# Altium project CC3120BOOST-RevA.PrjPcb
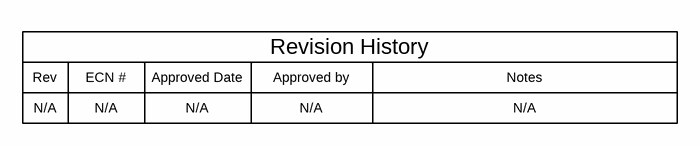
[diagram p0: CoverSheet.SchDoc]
CopyrightYear: 2015; EVM_Orderable: CC3120BOOST; PCB_Layout: Tessolve; PCB_Rev: A; PRJ_Customer: Public Release; PRJ_Engineer: Prajay Madhavan; PRJ_Number: WCS001; PRJ_Title: CC3120BOOST; SCH_Rev: A; TechSupport: http://www.ti.com/support; TID: N/A
4 sheets, 156 parts. Net scope: global (net labels, ports and power ports of the same name join across sheets).
Board file: CC3120BOOST-RevA.PcbDoc
Sheets:
  CoverSheet.SchDoc
  1.Engine.SchDoc
  2.HOST INTERFACE.SchDoc
  EVM_Hardware.SchDoc

## Sheet CoverSheet.SchDoc: Cover Sheet
size 431 x 279 mm; Date: Not shown in title block; ApprovedBy: Not shown in title block; CheckedBy: Not shown in title block; Author: Not shown in title block; CompanyName: Not shown in title block; Engineer: Not shown in title block; Organization: Not shown in title block; Address1: Not shown in title block; Address2: Not shown in title block; Address3: Not shown in title block; Address4: Not shown in title block; DocumentNumber: 1; Revision: Use project parameter SCH_Rev; SheetNumber: 1; SheetTotal: 4; PageSetup: Record=PageOptions¦CenterHorizontal=True¦CenterVertical=True¦PrintScale=1.00¦XCorrection=1.00¦YCorrection=1.00¦PrintKind=0¦BorderSize=5000000¦LeftOffset=0¦BottomOffset=0¦Orientation=2¦PaperLength=1000¦PaperWidth=1000¦Scale=100¦PaperSource=15¦PrintQuality=600¦MediaType=1¦DitherType=10¦PaperKind=Letter¦PrintScaleMode=1

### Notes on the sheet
- Rev
- N/A
- ECN #
- Approved Date
- Approved by
- Revision History
- Notes

## Sheet 1.Engine.SchDoc: Engine
size 558 x 431 mm; Date: Not shown in title block; ApprovedBy: Not shown in title block; CheckedBy: Not shown in title block; Author: Not shown in title block; CompanyName: Not shown in title block; Engineer: Not shown in title block; Organization: Not shown in title block; Address1: Not shown in title block; Address2: Not shown in title block; Address3: Not shown in title block; Address4: Not shown in title block; DocumentNumber: 2; Revision: Use project parameter SCH_Rev; SheetNumber: 2; SheetTotal: 4; PageSetup: Record=PageOptions¦CenterHorizontal=True¦CenterVertical=True¦PrintScale=1.00¦XCorrection=1.00¦YCorrection=1.00¦PrintKind=0¦BorderSize=5000000¦LeftOffset=0¦BottomOffset=0¦Orientation=2¦PaperLength=1000¦PaperWidth=1000¦Scale=100¦PaperSource=15¦PrintQuality=600¦MediaType=1¦DitherType=10¦PaperKind=Letter¦PrintScaleMode=1
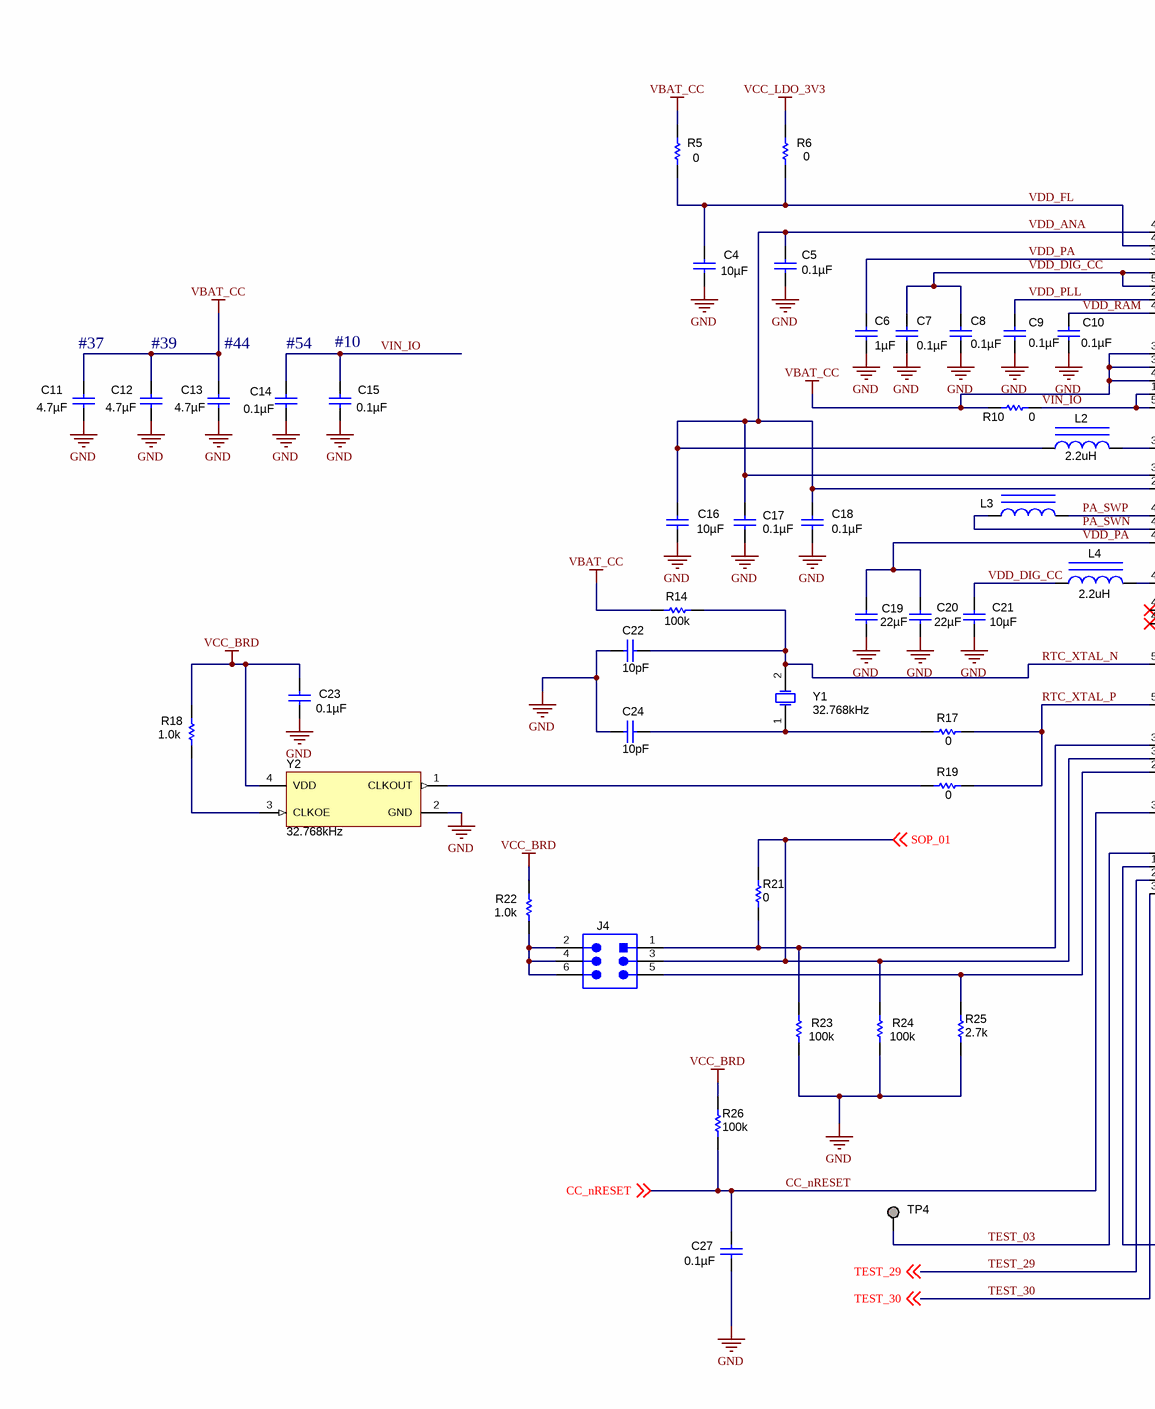
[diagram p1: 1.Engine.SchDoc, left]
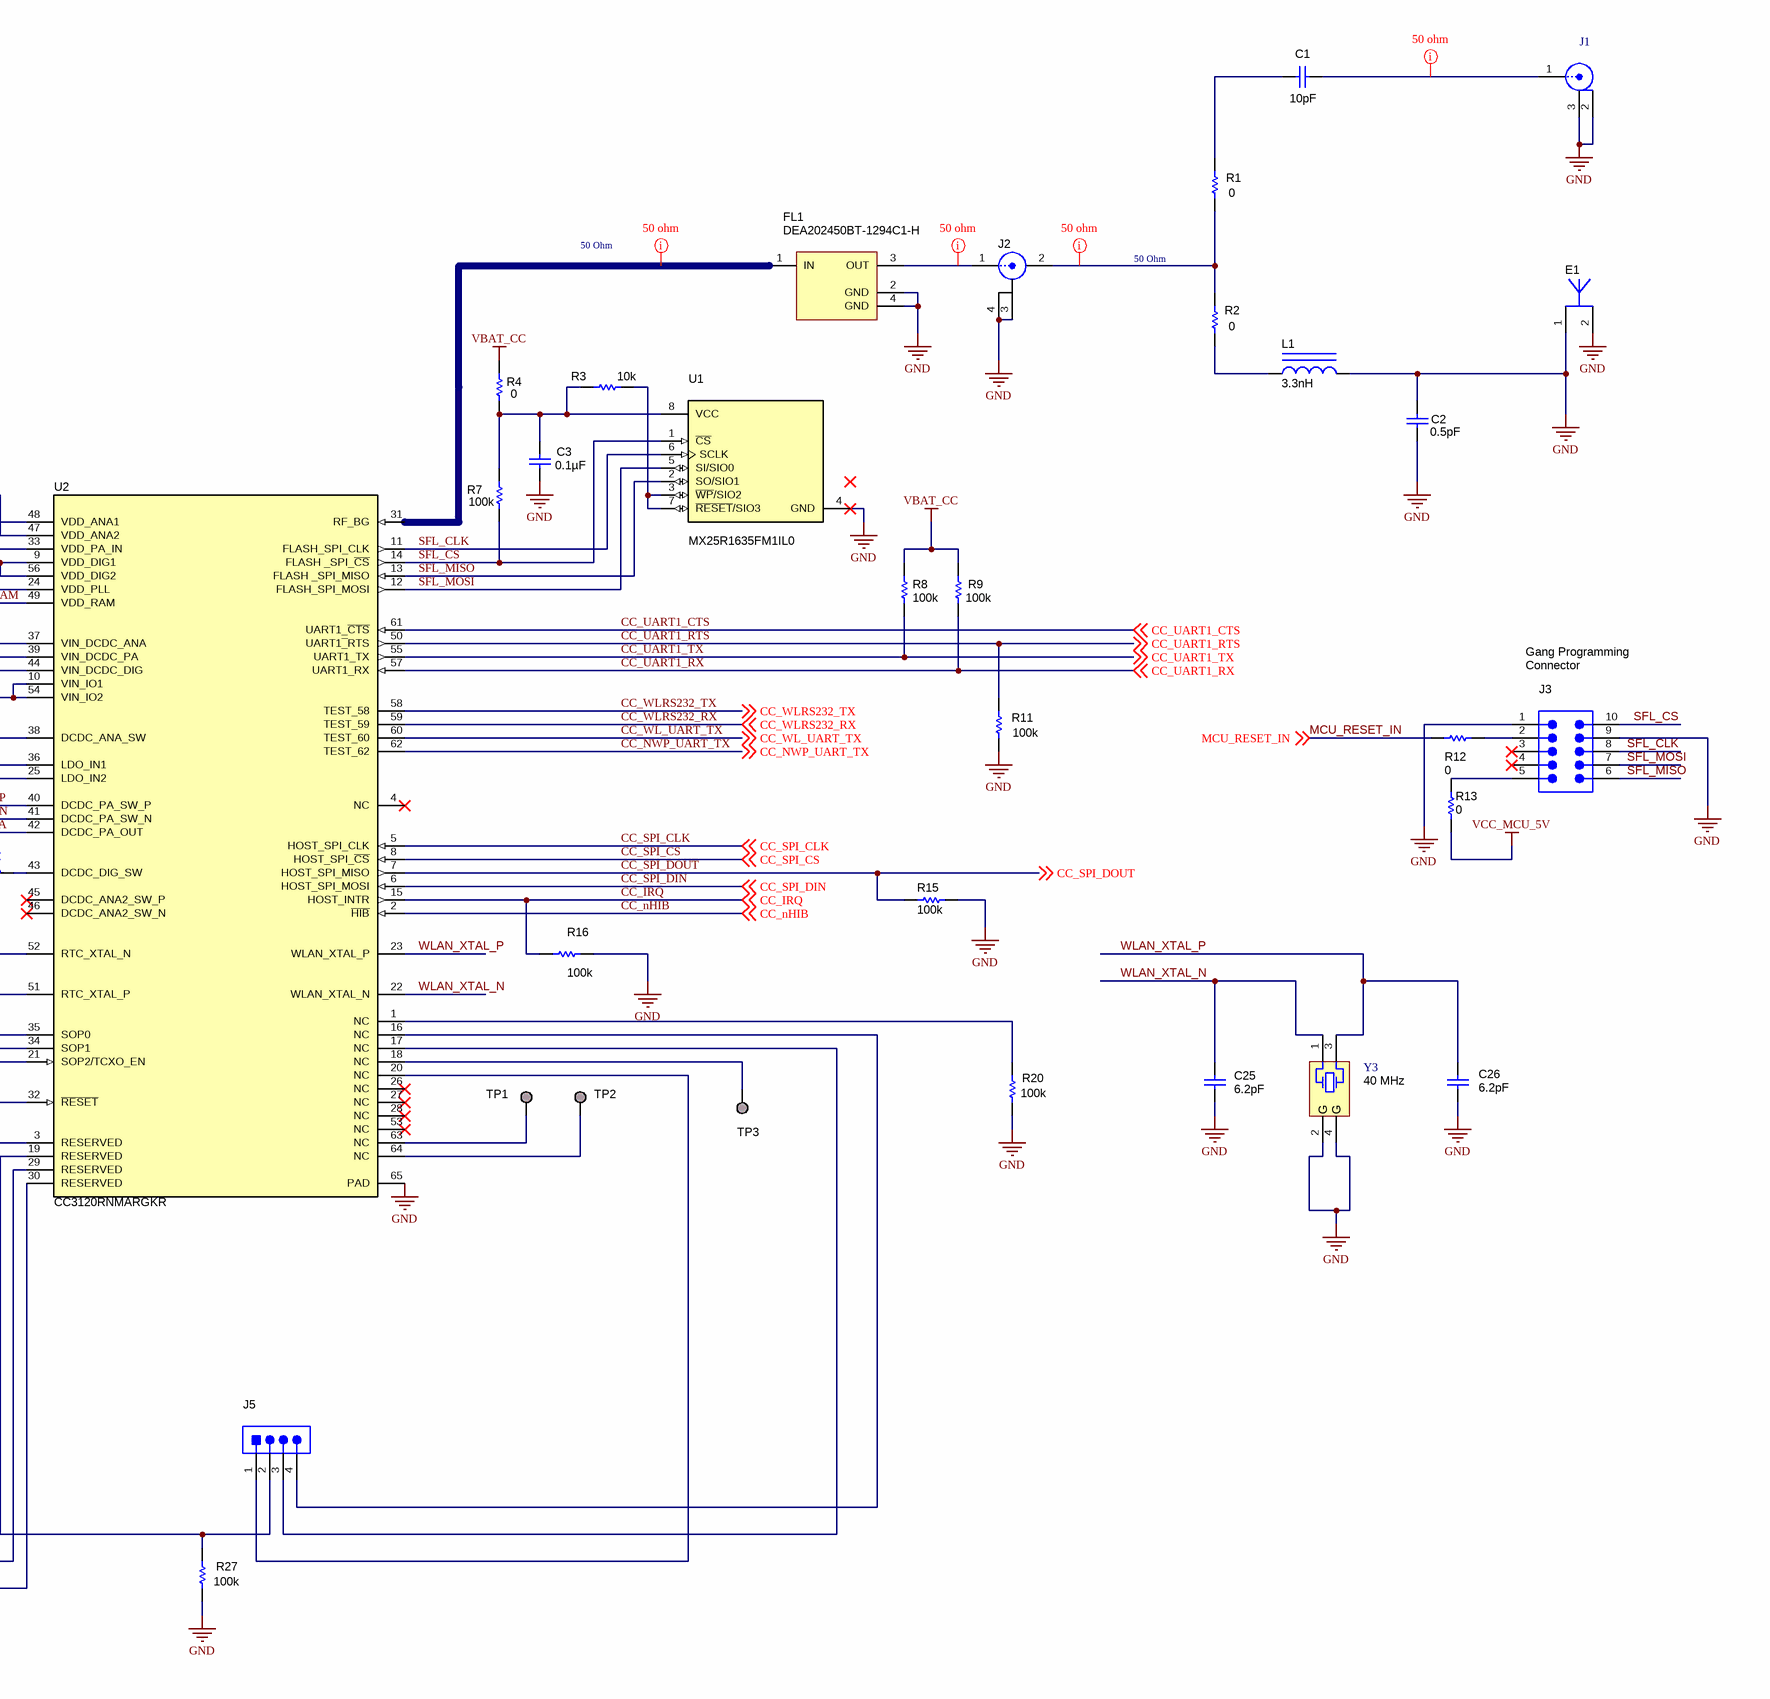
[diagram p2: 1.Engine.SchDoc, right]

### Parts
C1  ValueDisplayed: 10pF  [0402]  (hidden comment: 500R07S100JV4T)
C2  ValueDisplayed: 0.5pF  [0402]  (hidden comment: GRM1555C1HR50BA01D)
C3  ValueDisplayed: 0.1µF  [0402]  (hidden comment: C1005X5R1A104K050BA)
C4  ValueDisplayed: 10µF  [0603]  (hidden comment: GRM188R60J106ME47D)
C5  ValueDisplayed: 0.1µF  [0402]  (hidden comment: C1005X5R1A104K050BA)
C6  ValueDisplayed: 1µF  [0402]  (hidden comment: C1005X5R1A105K050BB)
C7  ValueDisplayed: 0.1µF  [0402]  (hidden comment: C1005X5R1A104K050BA)
C8  ValueDisplayed: 0.1µF  [0402]  (hidden comment: C1005X5R1A104K050BA)
C9  ValueDisplayed: 0.1µF  [0402]  (hidden comment: C1005X5R1A104K050BA)
C10  ValueDisplayed: 0.1µF  [0402]  (hidden comment: C1005X5R1A104K050BA)
C11  ValueDisplayed: 4.7µF  [0402]  (hidden comment: C1005X5R0J475M050BC)
C12  ValueDisplayed: 4.7µF  [0402]  (hidden comment: C1005X5R0J475M050BC)
C13  ValueDisplayed: 4.7µF  [0402]  (hidden comment: C1005X5R0J475M050BC)
C14  ValueDisplayed: 0.1µF  [0402]  (hidden comment: C1005X5R1A104K050BA)
C15  ValueDisplayed: 0.1µF  [0402]  (hidden comment: C1005X5R1A104K050BA)
C16  ValueDisplayed: 10µF  [0603]  (hidden comment: GRM188R60J106ME47D)
C17  ValueDisplayed: 0.1µF  [0402]  (hidden comment: C1005X5R1A104K050BA)
C18  ValueDisplayed: 0.1µF  [0402]  (hidden comment: C1005X5R1A104K050BA)
C19  ValueDisplayed: 22µF  [0603]  (hidden comment: C1608X5R0G226M080AA)
C20  ValueDisplayed: 22µF  [0603]  (hidden comment: C1608X5R0G226M080AA)
C21  ValueDisplayed: 10µF  [0603]  (hidden comment: GRM188R60J106ME47D)
C22  ValueDisplayed: 10pF  [0402]  (hidden comment: 500R07S100JV4T)
C23  ValueDisplayed: 0.1µF  [0402]  (hidden comment: C1005X5R1A104K050BA)
C24  ValueDisplayed: 10pF  [0402]  (hidden comment: 500R07S100JV4T)
C25  ValueDisplayed: 6.2pF  [0402]  (hidden comment: GRM1555C1H6R2CA01D)
C26  ValueDisplayed: 6.2pF  [0402]  (hidden comment: GRM1555C1H6R2CA01D)
C27  ValueDisplayed: 0.1µF  [0402]  (hidden comment: C1005X5R1A104K050BA)
E1  AH316M245001-T  [TAYO_AH316M]  (value not drawn)
FL1  DEA202450BT-1294C1-H  [TDK_DEA202450BT-1294C1-H]
J1  U.FL-R-SMT-1  [CONN_UFL-R-SMT-1]  (value not drawn)
J2  MM8030-2610RJ3  [MuRata_MM8030-2610]  (value not drawn)
J3  TC2050-IDC-430-FP  [TC2050-IDC-430-FP]  (value not drawn)  (no BOM)
J4  GRPB032VWVN-RC  [Sullins_GRPB032VWVN-RC]  (value not drawn)
J5  GRPB041VWVN-RC  [Sullins_GRPB041VWVN-RC]  (value not drawn)
L1  3.3nH  [IND_LQG15H]
L2  value 2.2uH  [1008]  (hidden comment: LQM2HPN2R2MG0L)
L3  LQM2HPN1R0MG0L  [1008]  (value not drawn)
L4  value 2.2uH  [1008]  (hidden comment: LQM2HPN2R2MG0L)
R1  ValueDisplayed: 0  [0402]  (hidden comment: ERJ-2GE0R00X)
R2  ValueDisplayed: 0  [0402]  (hidden comment: ERJ-2GE0R00X)
R3  ValueDisplayed: 10k  [0402]  (hidden comment: CRCW040210K0JNED)
R4  ValueDisplayed: 0  [0603]  (hidden comment: RC0603JR-070RL)
R5  ValueDisplayed: 0  [0603]  (hidden comment: RC0603JR-070RL)
R6  ValueDisplayed: 0  [0603]  (hidden comment: RC0603JR-070RL)
R7  ValueDisplayed: 100k  [0402]  (hidden comment: CRCW0402100KJNED)
R8  ValueDisplayed: 100k  [0402]  (hidden comment: CRCW0402100KJNED)
R9  ValueDisplayed: 100k  [0402]  (hidden comment: CRCW0402100KJNED)
R10  ValueDisplayed: 0  [0603]  (hidden comment: RC0603JR-070RL)
R11  ValueDisplayed: 100k  [0402]  (hidden comment: CRCW0402100KJNED)
R12  ValueDisplayed: 0  [0402]  (hidden comment: ERJ-2GE0R00X)
R13  ValueDisplayed: 0  [0402]  (hidden comment: ERJ-2GE0R00X)
R14  ValueDisplayed: 100k  [0402]  (hidden comment: CRCW0402100KJNED)
R15  ValueDisplayed: 100k  [0402]  (hidden comment: CRCW0402100KJNED)
R16  ValueDisplayed: 100k  [0402]  (hidden comment: CRCW0402100KJNED)
R17  ValueDisplayed: 0  [0402]  (hidden comment: ERJ-2GE0R00X)
R18  ValueDisplayed: 1.0k  [0402]  (hidden comment: CRCW04021K00JNED)
R19  ValueDisplayed: 0  [0402]  (hidden comment: ERJ-2GE0R00X)
R20  ValueDisplayed: 100k  [0402]  (hidden comment: CRCW0402100KJNED)
R21  ValueDisplayed: 0  [0402]  (hidden comment: ERJ-2GE0R00X)
R22  ValueDisplayed: 1.0k  [0402]  (hidden comment: CRCW04021K00JNED)
R23  ValueDisplayed: 100k  [0402]  (hidden comment: CRCW0402100KJNED)
R24  ValueDisplayed: 100k  [0402]  (hidden comment: CRCW0402100KJNED)
R25  ValueDisplayed: 2.7k  [0402]  (hidden comment: CRCW04022K70JNED)
R26  ValueDisplayed: 100k  [0402]  (hidden comment: CRCW0402100KJNED)
R27  ValueDisplayed: 100k  [0402]  (hidden comment: CRCW0402100KJNED)
TP1  TESTPOINT  [TP_H045P075]  (value not drawn)  (no BOM)
TP2  TESTPOINT  [TP_H045P075]  (value not drawn)  (no BOM)
TP3  TESTPOINT  [TP_H045P075]  (value not drawn)  (no BOM)
TP4  TESTPOINT  [TP_H045P075]  (value not drawn)  (no BOM)
U1  MX25R1635FM1IL0  [SOP-8_150MIL]
U2  CC3120RNMARGKR  [RGK0064B]
Y1  Frequency: 32.768kHz  [XTAL_ABS07]  (hidden comment: ABS07-32.768KHZ-9-T)
Y2  Frequency: 32.768kHz  [MC_OV-7604-C7]  (hidden comment: OV-7604-C7)
Y3  Frequency: 40 MHz  [Epson_FA-20H]  (hidden comment: Q24FA20H0039600)

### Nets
GND: C2.1 C2.2 C3.2 C4.2 C5.2 C6.2 C7.2 C8.2 C9.2 C10.2 C11.2 C12.2 C13.2 C14.2 C15.2 C16.2 C17.2 C18.2 C19.2 C20.2 C21.2 C22.2 C23.2 C24.2 C25.2 C26.2 C27.2 E1.1 E1.2 FL1.2(GND) FL1.4(GND) J1.2 J1.3 J2.3(GND) J2.4(GND) J3.1 J3.9 L1.2 R11.2 R15.2 R16.2 R20.2 R23.2 R24.2 R25.2 R27.2 U1.4(GND) U2.65(PAD) Y2.2(GND) Y3.2(GND) Y3.4(GND)
VBAT_CC: C11.1 C12.1 C13.1 R4.2 R5.2 R8.1 R9.1 R10.2 R14.1 U2.37(VIN_DCDC_ANA) U2.39(VIN_DCDC_PA) U2.44(VIN_DCDC_DIG)
VCC_BRD: C23.1 R18.1 R22.1 R26.1 Y2.4(VDD)
VCC_LDO_3V3: R6.2
VCC_MCU_5V: R13.1
CC_IRQ: R16.1 U2.15(HOST_INTR) ; off-sheet CC_IRQ
CC_nHIB: U2.2(~{HIB}) ; off-sheet CC_nHIB
CC_nRESET: C27.1 R26.2 U2.32(~{RESET}) ; off-sheet CC_nRESET
CC_NWP_UART_TX: U2.62(TEST_62) ; off-sheet CC_NWP_UART_TX
CC_SPI_CLK: U2.5(HOST_SPI_CLK) ; off-sheet CC_SPI_CLK
CC_SPI_CS: U2.8(HOST_SPI_~{CS}) ; off-sheet CC_SPI_CS
CC_SPI_DIN: U2.6(HOST_SPI_MOSI) ; off-sheet CC_SPI_DIN
CC_SPI_DOUT: R15.1 U2.7(HOST_SPI_MISO) ; off-sheet CC_SPI_DOUT
CC_UART1_CTS: U2.61(UART1_~{CTS}) ; off-sheet CC_UART1_CTS
CC_UART1_RTS: R11.1 U2.50(UART1~{_}RTS) ; off-sheet CC_UART1_RTS
CC_UART1_RX: R9.2 U2.57(UART1_RX) ; off-sheet CC_UART1_RX
CC_UART1_TX: R8.2 U2.55(UART1_TX) ; off-sheet CC_UART1_TX
CC_WL_UART_TX: U2.60(TEST_60) ; off-sheet CC_WL_UART_TX
CC_WLRS232_RX: U2.59(TEST_59) ; off-sheet CC_WLRS232_RX
CC_WLRS232_TX: U2.58(TEST_58) ; off-sheet CC_WLRS232_TX
MCU_RESET_IN: R12.2 ; off-sheet MCU_RESET_IN
PA_SWN: L3.1 U2.41(DCDC_PA_SW_N)
PA_SWP: L3.2 U2.40(DCDC_PA_SW_P)
RTC_XTAL_N: C22.1 R14.2 U2.52(RTC_XTAL_N) Y1.2(OSC2)
RTC_XTAL_P: R17.2 R19.2 U2.51(RTC_XTAL_P)
SFL_CLK: J3.8 U1.6(SCLK) U2.11(FLASH_SPI_CLK)
SFL_CS: J3.10 R7.2 U1.1(~{CS}) U2.14(FLASH__SPI_~{CS})
SFL_MISO: J3.6 U1.2(SO/SIO1) U2.13(FLASH__SPI_MISO)
SFL_MOSI: J3.7 U1.5(SI/SIO0) U2.12(FLASH_SPI_MOSI)
SOP_01: J4.3 R21.2 R24.1 U2.34(SOP1) ; off-sheet SOP_01
TEST_03: TP4.1 U2.3(RESERVED)
TEST_29: U2.29(RESERVED) ; off-sheet TEST_29
TEST_30: U2.30(RESERVED) ; off-sheet TEST_30
VDD_ANA: C5.1 C16.1 C17.1 C18.1 L2.1 U2.25(LDO_IN2) U2.36(LDO_IN1) U2.48(VDD_ANA1)
VDD_DIG_CC: C7.1 C8.1 C21.1 L4.1 U2.9(VDD_DIG1) U2.56(VDD_DIG2)
VDD_FL: C4.1 R5.1 R6.1 U2.47(VDD_ANA2)
VDD_PA: C6.1 C19.1 C20.1 U2.33(VDD_PA_IN) U2.42(DCDC_PA_OUT)
VDD_PLL: C9.1 U2.24(VDD_PLL)
VDD_RAM: C10.1 U2.49(VDD_RAM)
VIN_IO: C14.1 C15.1 R10.1 U2.10(VIN_IO1) U2.54(VIN_IO2)
WLAN_XTAL_N: C25.1 U2.22(WLAN_XTAL_N) Y3.1
WLAN_XTAL_P: C26.1 U2.23(WLAN_XTAL_P) Y3.3
NetC1_1: C1.1 R1.2
NetC1_2: C1.2 J1.1
NetC3_1: C3.1 R3.1 R4.1 R7.1 U1.8(VCC)
NetC24_1: C24.1 R17.1 Y1.1(OSC1)
NetFL1_1: FL1.1(IN) U2.31(RF_BG)
NetFL1_3: FL1.3(OUT) J2.1(IN)
NetJ2_2: J2.2(OUT) R1.1 R2.2
NetJ3_2: J3.2 R12.1
NetJ3_5: J3.5 R13.2
NetJ4_1: J4.1 R21.1 R23.1 U2.35(SOP0)
NetJ4_2: J4.2 J4.4 J4.6 R22.2
NetJ4_5: J4.5 R25.1 U2.21(SOP2/TCXO_EN)
NetJ5_1: J5.1 U2.20(NC)
NetJ5_2: J5.2 R27.1 U2.19(RESERVED)
NetJ5_3: J5.3 U2.17(NC)
NetJ5_4: J5.4 U2.16(NC)
NetL1_1: L1.1 R2.1
NetL2_2: L2.2 U2.38(DCDC_ANA_SW)
NetL4_2: L4.2 U2.43(DCDC_DIG_SW)
NetR3_2: R3.2 U1.3(~{WP}/SIO2) U1.7(~{RESET}/SIO3)
NetR18_2: R18.2 Y2.3(CLKOE)
NetR19_1: R19.1 Y2.1(CLKOUT)
NetR20_1: R20.1 U2.1(NC)
NetTP1_1: TP1.1 U2.63(NC)
NetTP2_1: TP2.1 U2.64(NC)
NetTP3_1: TP3.1 U2.18(NC)

Not connected (* = marked no-connect by the designer): J3 3* 4*; U2 4(NC)* 26(NC)* 27(NC)* 28(NC)* 45(DCDC_ANA2_SW_P)* 46(DCDC_ANA2_SW_N)* 53(NC)*

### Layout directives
net class 50 ohm: NetC1_2, NetFL1_1, NetFL1_3, NetJ2_2

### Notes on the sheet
- 50 Ohm
- #37
- #39
- #44
- #54
- #10
- Gang Programming
  Connector

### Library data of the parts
C1 C22 C24 = 500R07S100JV4T: CAP, CERM, 10 pF, 50 V, +/- 5%, C0G/NP0, 0402; Manufacturer: Johanson Technology; Polarized: N; CompType: Capacitor; Value: 10pF; U/M: EA; Cap_F: 0.00000000001; Tolerance_%: 5; Value1: Unknown; VDC_V: 50; Value2: 50V; TaMin_C: -55; TaMax_C: 125
C2 = GRM1555C1HR50BA01D: CAP, CERM, 0.5 pF, 50 V, +/- 20%, C0G/NP0, 0402; Manufacturer: MuRata; Polarized: N; CompType: Capacitor; Value: 0.5pF; U/M: EA; Cap_F: 0.0000000000005; Tolerance_%: 20; Value1: Unknown; VDC_V: 50; Value2: 50V; TaMin_C: -55; TaMax_C: 125
C3 C5 C7-C10 C14 C15 C17 C18 C23 C27 = C1005X5R1A104K050BA: CAP, CERM, 0.1 µF, 10 V, +/- 10%, X5R, 0402; Manufacturer: TDK; Polarized: N; CompType: Capacitor; Value: 0.1uF; U/M: EA; Cap_F: 0.0000001; Tolerance_%: 10; Value1: Unknown; Value2: 10V; TaMin_C: -55; TaMax_C: 85
C4 C16 C21 = GRM188R60J106ME47D: CAP, CERM, 10 µF, 6.3 V, +/- 20%, X5R, 0603; Manufacturer: MuRata; Polarized: N; CompType: Capacitor; Value: 10uF; U/M: EA; Cap_F: 0.00001; Tolerance_%: 20; ESR_ohm: 0.009; Value1: 0.009 ohm; VDC_V: 6.3; Value2: 6.3V; IRMS_A: 2.74; TaMin_C: -55; TaMax_C: 125
C6 = C1005X5R1A105K050BB: CAP, CERM, 1 µF, 10 V, +/- 10%, X5R, 0402; Manufacturer: TDK; Polarized: N; CompType: Capacitor; Value: 1uF; U/M: EA; Cap_F: 0.000001; Tolerance_%: 10; Value1: Unknown; Value2: 10V; TaMin_C: -55; TaMax_C: 85
C11-C13 = C1005X5R0J475M050BC: CAP, CERM, 4.7 µF, 6.3 V, +/- 20%, X5R, 0402; Manufacturer: TDK; Polarized: N; CompType: Capacitor; Value: 4.7uF; U/M: EA; Cap_F: 0.0000047; Tolerance_%: 20; Value1: Unknown; VDC_V: 6.3; Value2: 6.3V; TaMin_C: -55; TaMax_C: 85
C19 C20 = C1608X5R0G226M080AA: CAP, CERM, 22 µF, 4 V, +/- 20%, X5R, 0603; Manufacturer: TDK; Polarized: N; CompType: Capacitor; Value: 22uF; U/M: EA; Cap_F: 0.000022; Tolerance_%: 20; Value1: Unknown; VDC_V: 4; Value2: 4V; TaMin_C: -55; TaMax_C: 85
C25 C26 = GRM1555C1H6R2CA01D: CAP, CERM, 6.2 pF, 50 V, +/- 5%, C0G/NP0, 0402; Manufacturer: MuRata; Polarized: N; CompType: Capacitor; Value: 6.2pF; U/M: EA; Cap_F: 0.0000000000062; Tolerance_%: 5; Value1: Unknown; VDC_V: 50; Value2: 50V; TaMin_C: -55; TaMax_C: 125
E1 = AH316M245001-T: ANT BLUETOOTH W-LAN ZIGBEE WIMAX, SMD; Manufacturer: Taiyo Yuden; SymbolCreator: a0411947; CompType: Antenna
FL1 = DEA202450BT-1294C1-H: Multilayer Chip Band Pass Filter For 2.4GHz W-LAN/Bluetooth, SMD; Manufacturer: TDK; SymbolCreator: Altium; Value: 1.02 dB
J1 = U.FL-R-SMT-1: Connector, Ultra-Mini Coaxial, SMD; Manufacturer: Hirose Electric Co. Ltd.; SymbolCreator: a0412235; U/M: EA
J2 = MM8030-2610RJ3: Coaxial Connectors with Switch, 50 Ohm, SMD; Manufacturer: MuRata; SymbolCreator: Altium; U/M: EA
J3 = TC2050-IDC-430-FP: Footprint for TC2050-IDC-430; Manufacturer: Tag-Connect; SymbolCreator: a0799628; CompType: Receptacle; U/M: EA; Note: Footprint only, to mate with Tag-Connect cable P/N TC2050-IDC-430
J4 = GRPB032VWVN-RC: Header, 50mil, 3x2, Gold, TH; Manufacturer: Sullins Connector Solutions; SymbolCreator: a0412235; U/M: EA
J5 = GRPB041VWVN-RC: Header, 50mil, 4x1, Gold, TH; Manufacturer: Sullins Connector Solutions; SymbolCreator: a0412235; U/M: EA
L1 = LQG15HS3N3S02D: Inductor, Multilayer, Air Core, 3.3 nH, 0.3 A, 0.17 ohm, SMD; Manufacturer: MuRata; Ind_H: 3.3E-9; Imax_A: 0.3; Irms: 0.3A @ C rise; Isat: 0.3A @ % inductance drop; DCR_ohm: 0.17; Value2: 0.3A
L2 L4 = LQM2HPN2R2MG0L: Inductor, Multilayer, Ferrite, 2.2 µH, 1.3 A, 0.08 ohm, SMD; Manufacturer: MuRata; Ind_H: 2.2E-6; ValueDisplayed: 2.2µH; Imax_A: 1.3; Irms: 1.3A @ 40C rise; DCR_ohm: 0.08; Value2: 1.3A
L3 = LQM2HPN1R0MG0L: Inductor, Multilayer, Ferrite, 1 µH, 1.6 A, 0.055 ohm, SMD; Manufacturer: MuRata; Value: 1uH; Ind_H: 1.0E-6; ValueDisplayed: 1µH; Imax_A: 1.6; Irms: 1.6A @ 40C rise; DCR_ohm: 0.055; Value2: 1.6A
R1 R2 R12 R13 R17 R19 R21 = ERJ-2GE0R00X: RES, 0, 5%, 0.063 W, 0402; Manufacturer: Panasonic; CompType: Resistor; Value: 0; Value_Code: 0000; Tolerance_%: 5; Power_W: 0.063; Value2: 0.063W; VDC_V: 50; TempCo: 600 ppm/C; EIA_Code: E24; U/M: EA
R3 = CRCW040210K0JNED: RES, 10 k, 5%, 0.063 W, 0402; Manufacturer: Vishay-Dale; CompType: Resistor; Value: 10k; Res_ohm: 10000; Value_Code: 10k0; Tolerance_%: 5; Power_W: 0.063; Value2: 0.063W; VDC_V: 50; TempCo: 200 ppm/C; EIA_Code: E24; U/M: EA
R4-R6 R10 = RC0603JR-070RL: RES, 0, 5%, 0.1 W, 0603; Manufacturer: Yageo America; CompType: Resistor; Value: 0; Value_Code: 0000; Tolerance_%: 5; Power_W: 0.1; Value2: 0.1W; VDC_V: 50; TempCo: 200 ppm/C; EIA_Code: E24; U/M: EA
R7-R9 R11 R14-R16 R20 R23 R24 R26 R27 = CRCW0402100KJNED: RES, 100 k, 5%, 0.063 W, 0402; Manufacturer: Vishay-Dale; CompType: Resistor; Value: 100k; Res_ohm: 100000; Tolerance_%: 5; Power_W: 0.063; Value2: 0.063W; VDC_V: 50; TempCo: 200 ppm/C; EIA_Code: E24; U/M: EA
R18 R22 = CRCW04021K00JNED: RES, 1.0 k, 5%, 0.063 W, 0402; Manufacturer: Vishay-Dale; CompType: Resistor; Value: 1.0k; Res_ohm: 1000; Value_Code: 1k00; Tolerance_%: 5; Power_W: 0.063; Value2: 0.063W; VDC_V: 50; TempCo: 200 ppm/C; EIA_Code: E24; U/M: EA
R25 = CRCW04022K70JNED: RES, 2.7 k, 5%, 0.063 W, 0402; Manufacturer: Vishay-Dale; CompType: Resistor; Value: 2.7k; Res_ohm: 2700; Value_Code: 2k70; Tolerance_%: 5; Power_W: 0.063; Value2: 0.063W; VDC_V: 50; TempCo: 200 ppm/C; EIA_Code: E24; U/M: EA; SizeArea_mm2: 0.5; SizeX_mm: 1; SizeZ_mm: 0.6; AEC Category: Q200
TP1-TP4 = TP_H0.45P0.75: Manufacturer: Texas Instruments; CompType: Pad
U1 = MX25R1635FM1IL0: ULTRA LOW POWER, 16M-BIT [x 1/x 2/x 4] CMOS MXSMIO(SERIAL MULTI I/O) FLASH MEMORY, SOP-8; Manufacturer: Macronix International Co., LTD; SymbolCreator: Altium
U2 = CC3120RNMARGKR: SimpleLink Wi-Fi Network Processor, Internet-of-Things Solution for MCU Applications, RGK0064B (VQFN-64); Alternate PartNumber: CC3120RNMARGKT; Manufacturer: Texas Instruments; SymbolCreator: Altium; CompType: IC; U/M: EA; SizeArea_mm2: 81; SizeAreaWB_mm2: 121; SizeX_mm: 9; SizeZ_mm: 1
Y1 = ABS07-32.768KHZ-9-T: CRYSTAL, 32.768KHZ, 9PF, SMD; Manufacturer: Abracon Corportation; SymbolCreator: a0412235; U/M: EA; TaMin_C: -40; TaMax_C: 85; Frequency Stability: ±20ppm
Y2 = OV-7604-C7: Low Power Clock Oscillator, 32.768 kHz, SMD; Manufacturer: Micro Crystal AG; SymbolCreator: a0412235; U/M: EA; TaMin_C: -40; TaMax_C: 85
Y3 = Q24FA20H0039600: Crystal, 40MHz, 8pF, SMD; Manufacturer: Epson; SymbolCreator: a0412235; U/M: EA; TaMin_C: -30; TaMax_C: 85; Frequency Stability: ±7ppm

## Sheet 2.HOST INTERFACE.SchDoc: Host Interface
size 558 x 431 mm; Date: Not shown in title block; ApprovedBy: Not shown in title block; CheckedBy: Not shown in title block; Author: Not shown in title block; CompanyName: Not shown in title block; Engineer: Not shown in title block; Organization: Not shown in title block; Address1: Not shown in title block; Address2: Not shown in title block; Address3: Not shown in title block; Address4: Not shown in title block; DocumentNumber: 3; Revision: Use project parameter SCH_Rev; SheetNumber: 3; SheetTotal: 4; PageSetup: Record=PageOptions¦CenterHorizontal=True¦CenterVertical=True¦PrintScale=1.00¦XCorrection=1.00¦YCorrection=1.00¦PrintKind=0¦BorderSize=5000000¦LeftOffset=0¦BottomOffset=0¦Orientation=2¦PaperLength=1000¦PaperWidth=1000¦Scale=100¦PaperSource=15¦PrintQuality=600¦MediaType=1¦DitherType=10¦PaperKind=Letter¦PrintScaleMode=1
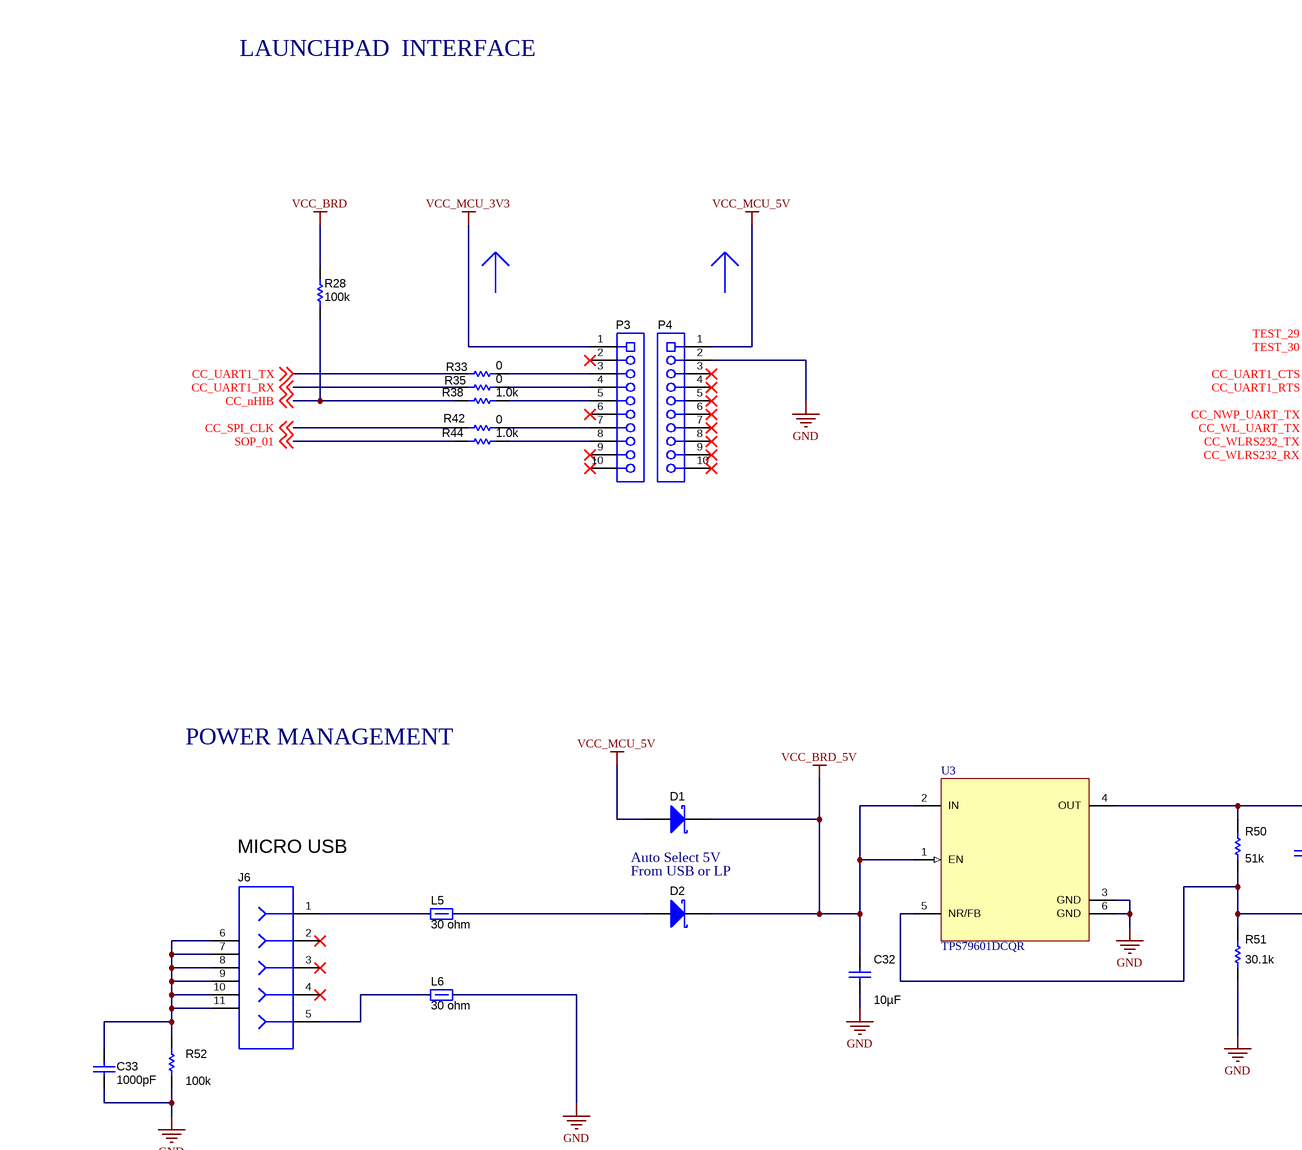
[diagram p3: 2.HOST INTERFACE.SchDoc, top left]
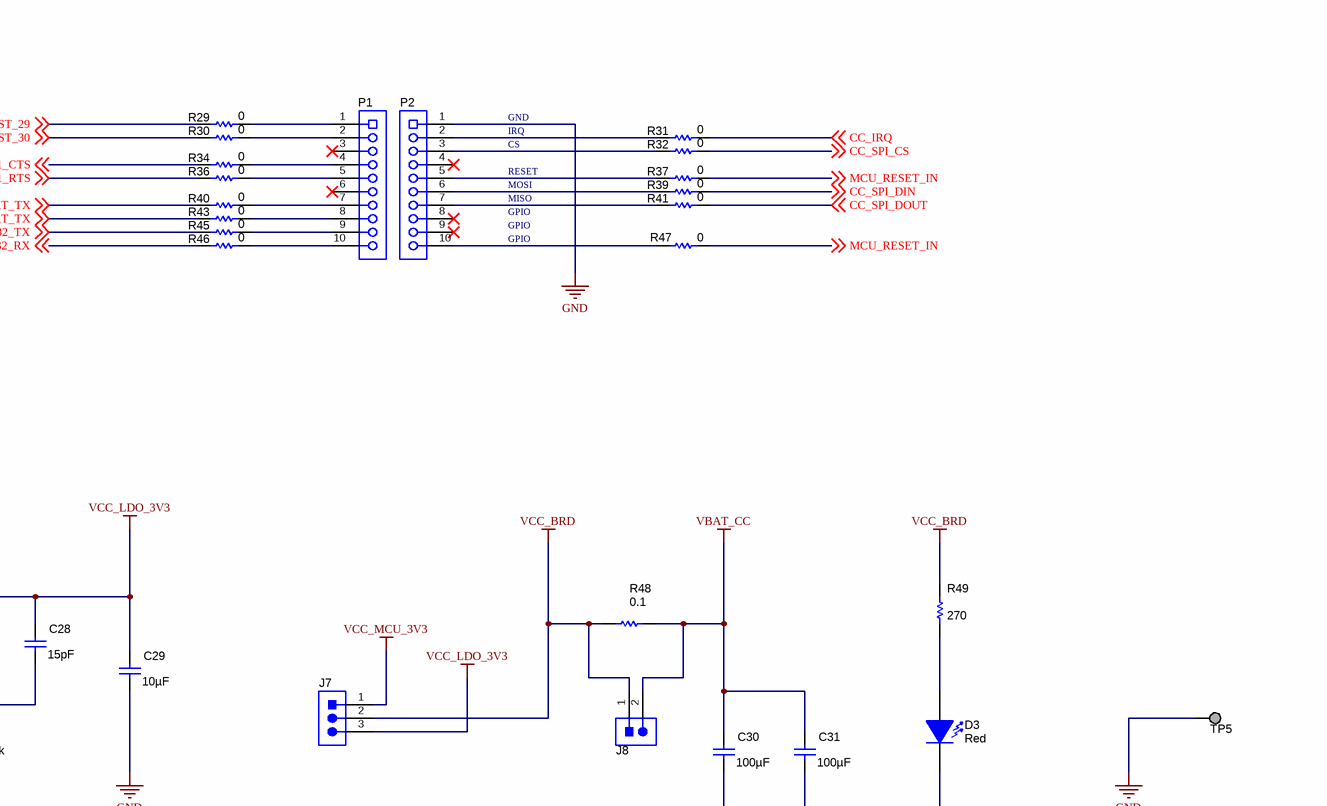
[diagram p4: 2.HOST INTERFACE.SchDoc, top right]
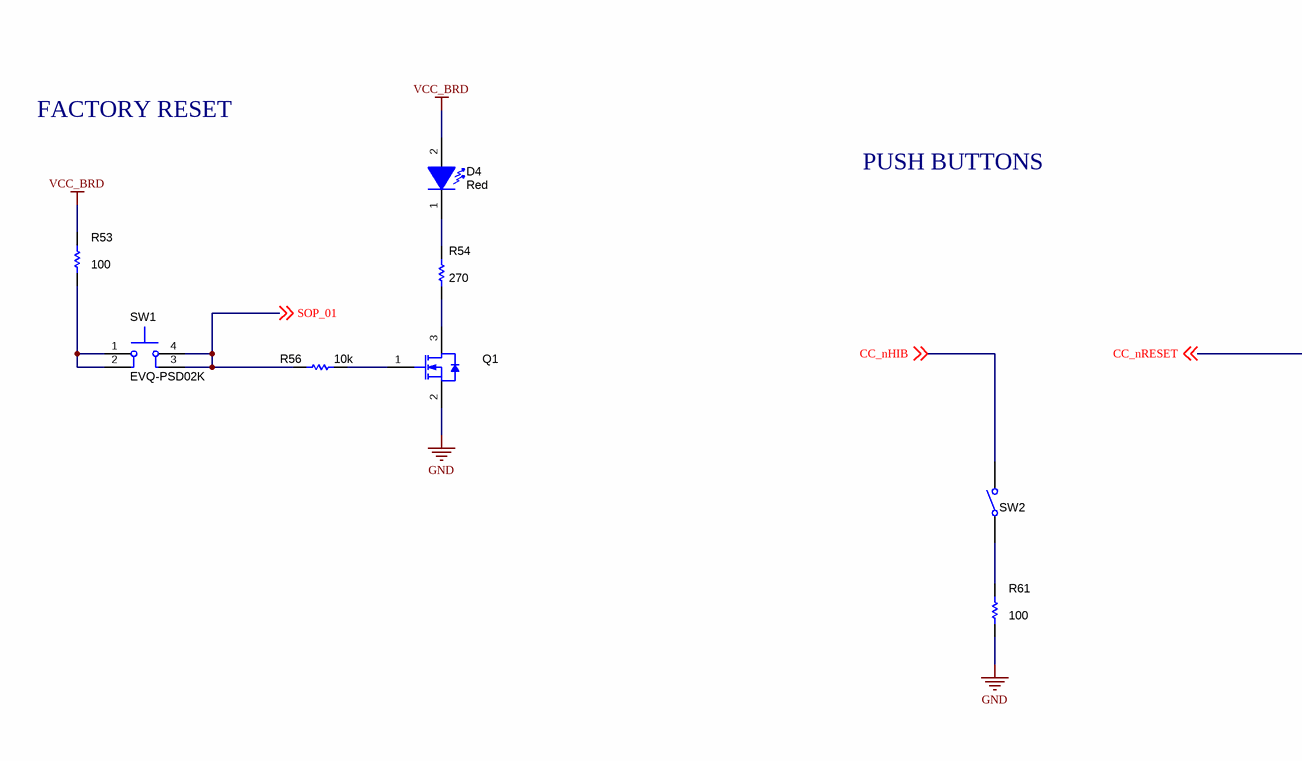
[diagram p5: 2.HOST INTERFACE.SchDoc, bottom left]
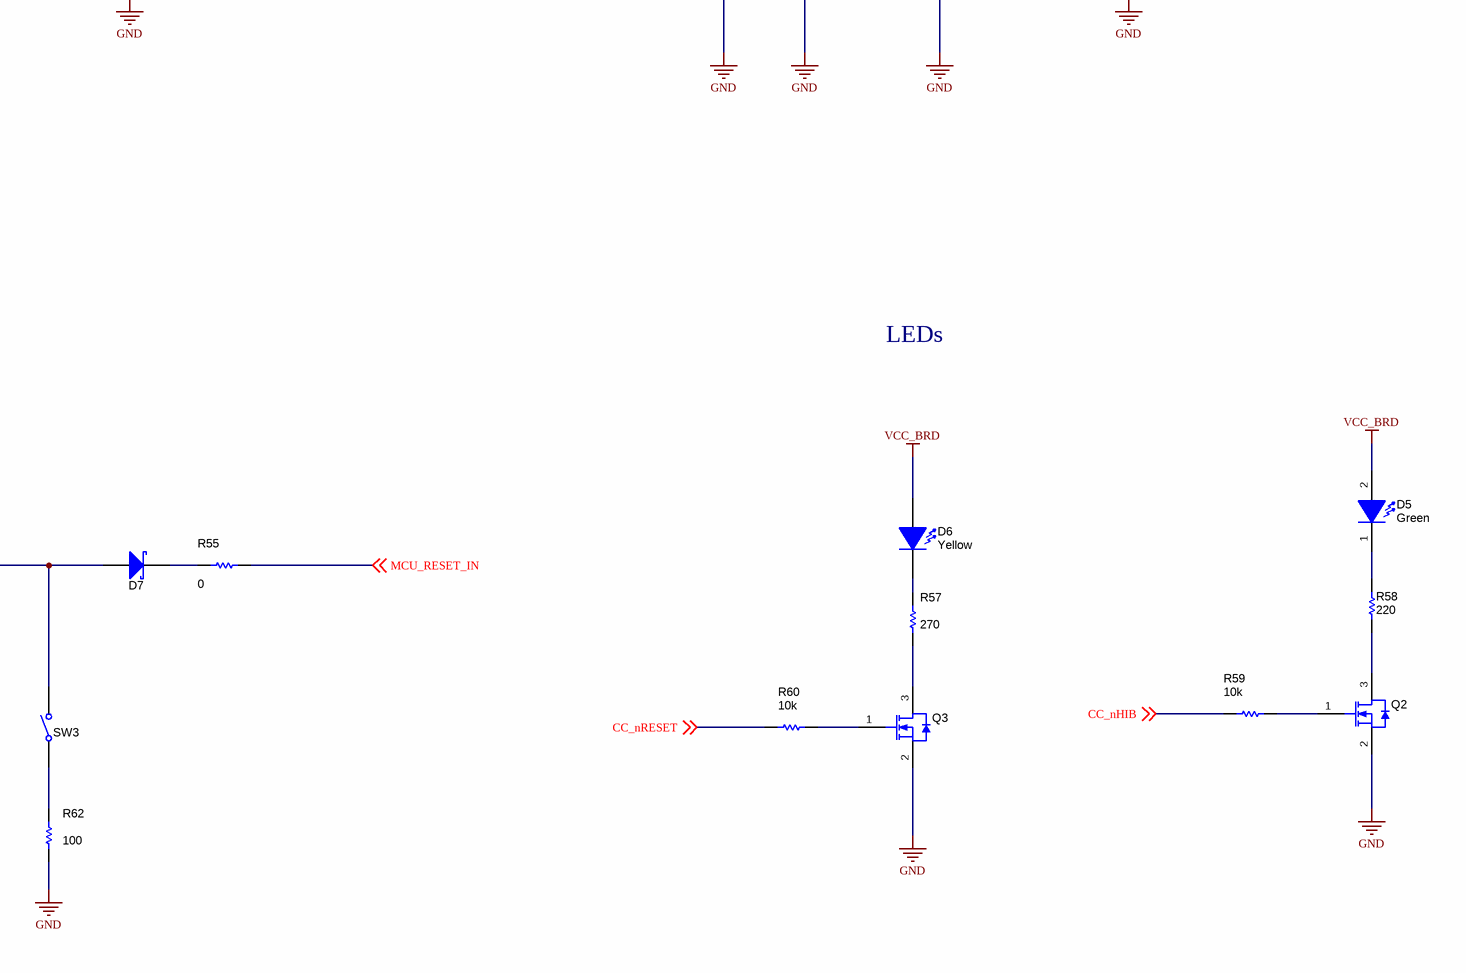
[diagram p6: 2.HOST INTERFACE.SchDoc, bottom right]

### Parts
C28  ValueDisplayed: 15pF  [0402]  (hidden comment: GRM1555C1H150JA01D)
C29  ValueDisplayed: 10µF  [0805_HV]  (hidden comment: GRM21BR61A106KE19L)
C30  ValueDisplayed: 100µF  [1206]  (hidden comment: GRM31CR60J107ME39L)
C31  ValueDisplayed: 100µF  [1206]  (hidden comment: GRM31CR60J107ME39L)
C32  ValueDisplayed: 10µF  [0805_HV]  (hidden comment: GRM21BR61A106KE19L)
C33  ValueDisplayed: 1000pF  [0603]  (hidden comment: GRM188R61H102KA01D)
D1  MBR130T1G  [SOD-123]  (value not drawn)
D2  MBR130T1G  [SOD-123]  (value not drawn)
D3  value Red  [SML-31_Red]  (hidden comment: SML-311UTT86)
D4  value Red  [WL-SMCW_RED]  (hidden comment: 150060RS75000)
D5  value Green  [WL-SMCW_GREEN]  (hidden comment: 150060GS75000)
D6  value Yellow  [WL-SMCW_YELLOW]  (hidden comment: 150060YS75000)
D7  CD0603-B00340  [Diode_0603]  (value not drawn)
J6  105017-0001  [CONN_105017-0001]  (value not drawn)
J7  TSW-103-07-G-S  [TSW-103-07-G-S]  (value not drawn)
J8  HMTSW-102-07-G-S-240  [SAMTEC_HMTSW-102-07-G-S-240]  (value not drawn)
L5  value 30 ohm  [0805_HV]  (hidden comment: MMZ2012R300A)
L6  value 30 ohm  [0805_HV]  (hidden comment: MMZ2012R300A)
P1  SSW-110-23-F-S  [CONN_SSW-110-23-F-S]  (value not drawn)
P2  SSW-110-23-F-S  [CONN_SSW-110-23-F-S]  (value not drawn)
P3  SSW-110-23-F-S  [CONN_SSW-110-23-F-S]  (value not drawn)
P4  SSW-110-23-F-S  [CONN_SSW-110-23-F-S]  (value not drawn)
Q1  BSS138  [SOT-23]  (value not drawn)
Q2  BSS138  [SOT-23]  (value not drawn)
Q3  BSS138  [SOT-23]  (value not drawn)
R28  ValueDisplayed: 100k  [0603]  (hidden comment: CRCW0603100KFKEA)
R29  ValueDisplayed: 0  [0402]  (hidden comment: ERJ-2GE0R00X)
R30  ValueDisplayed: 0  [0402]  (hidden comment: ERJ-2GE0R00X)
R31  ValueDisplayed: 0  [0402]  (hidden comment: ERJ-2GE0R00X)
R32  ValueDisplayed: 0  [0402]  (hidden comment: ERJ-2GE0R00X)
R33  ValueDisplayed: 0  [0402]  (hidden comment: ERJ-2GE0R00X)
R34  ValueDisplayed: 0  [0402]  (hidden comment: ERJ-2GE0R00X)
R35  ValueDisplayed: 0  [0402]  (hidden comment: ERJ-2GE0R00X)
R36  ValueDisplayed: 0  [0402]  (hidden comment: ERJ-2GE0R00X)
R37  ValueDisplayed: 0  [0402]  (hidden comment: ERJ-2GE0R00X)
R38  ValueDisplayed: 1.0k  [0402]  (hidden comment: CRCW04021K00JNED)
R39  ValueDisplayed: 0  [0402]  (hidden comment: ERJ-2GE0R00X)
R40  ValueDisplayed: 0  [0402]  (hidden comment: ERJ-2GE0R00X)
R41  ValueDisplayed: 0  [0402]  (hidden comment: ERJ-2GE0R00X)
R42  value 0  [0402]  (hidden comment: ERJ-2GE0R00X)
R43  ValueDisplayed: 0  [0402]  (hidden comment: ERJ-2GE0R00X)
R44  ValueDisplayed: 1.0k  [0402]  (hidden comment: CRCW04021K00JNED)
R45  ValueDisplayed: 0  [0402]  (hidden comment: ERJ-2GE0R00X)
R46  ValueDisplayed: 0  [0402]  (hidden comment: ERJ-2GE0R00X)
R47  ValueDisplayed: 0  [0402]  (hidden comment: ERJ-2GE0R00X)
R48  ValueDisplayed: 0.1  [0805_HV]  (hidden comment: CRM0805-FX-R100ELF)
R49  ValueDisplayed: 270  [0603]  (hidden comment: CRCW0603270RJNEA)
R50  ValueDisplayed: 51k  [0402]  (hidden comment: CRCW040251K0JNED)
R51  ValueDisplayed: 30.1k  [0402]  (hidden comment: CRCW040230K1FKED)
R52  ValueDisplayed: 100k  [0402]  (hidden comment: CRCW0402100KJNED)
R53  ValueDisplayed: 100  [0402]  (hidden comment: ERJ-2RKF1000X)
R54  ValueDisplayed: 270  [0603]  (hidden comment: CRCW0603270RJNEA)
R55  ValueDisplayed: 0  [0603]  (hidden comment: ERJ-3GEY0R00V)
R56  ValueDisplayed: 10k  [0402]  (hidden comment: CRCW040210K0JNED)
R57  ValueDisplayed: 270  [0603]  (hidden comment: CRCW0603270RJNEA)
R58  ValueDisplayed: 220  [0603]  (hidden comment: CRCW0603220RJNEA)
R59  ValueDisplayed: 10k  [0402]  (hidden comment: CRCW040210K0JNED)
R60  ValueDisplayed: 10k  [0402]  (hidden comment: CRCW040210K0JNED)
R61  ValueDisplayed: 100  [0402]  (hidden comment: ERJ-2RKF1000X)
R62  ValueDisplayed: 100  [0402]  (hidden comment: ERJ-2RKF1000X)
SW1  EVQ-PSD02K  [SW_EVQ-PSD02K]
SW2  MJTP1117  [SW_MJTP1117]  (value not drawn)
SW3  MJTP1117  [SW_MJTP1117]  (value not drawn)
TP5  TESTPOINT  [TP_H045P075]  (value not drawn)  (no BOM)
U3  TPS79601DCQR  [DCQ0006A_N]

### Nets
GND: C29.2 C30.2 C31.2 C32.2 C33.2 D3.1(K) L6.1 P2.1 P4.2 Q1.2(S) Q2.2(S) Q3.2(S) R51.1 R52.2 R61.1 R62.1 TP5.1 U3.3(GND) U3.6(GND)
VBAT_CC: C30.1 C31.1 J8.2 R48.2
VCC_BRD: D4.2(A) D5.2(A) D6.2(A) J7.2 J8.1 R28.2 R48.1 R49.1 R53.2
VCC_BRD_5V: C32.1 D1.1(K) D2.1(K) U3.1(EN) U3.2(IN)
VCC_LDO_3V3: C28.1 C29.1 J7.3 R50.2 U3.4(OUT)
VCC_MCU_3V3: J7.1 P3.1
VCC_MCU_5V: D1.2(A) P4.1
CC_IRQ: R31.2 ; off-sheet CC_IRQ
CC_nHIB: R28.1 R38.1 R59.1 SW2.2 ; off-sheet CC_nHIB
CC_nRESET: D7.2(A) R60.1 SW3.2 ; off-sheet CC_nRESET
CC_NWP_UART_TX: R40.1 ; off-sheet CC_NWP_UART_TX
CC_SPI_CLK: R42.1 ; off-sheet CC_SPI_CLK
CC_SPI_CS: R32.2 ; off-sheet CC_SPI_CS
CC_SPI_DIN: R39.2 ; off-sheet CC_SPI_DIN
CC_SPI_DOUT: R41.2 ; off-sheet CC_SPI_DOUT
CC_UART1_CTS: R34.1 ; off-sheet CC_UART1_CTS
CC_UART1_RTS: R36.1 ; off-sheet CC_UART1_RTS
CC_UART1_RX: R35.1 ; off-sheet CC_UART1_RX
CC_UART1_TX: R33.1 ; off-sheet CC_UART1_TX
CC_WL_UART_TX: R43.1 ; off-sheet CC_WL_UART_TX
CC_WLRS232_RX: R46.1 ; off-sheet CC_WLRS232_RX
CC_WLRS232_TX: R45.1 ; off-sheet CC_WLRS232_TX
MCU_RESET_IN: R37.2 R47.2 R55.2 ; off-sheet MCU_RESET_IN
SOP_01: R44.1 R56.1 SW1.3 SW1.4 ; off-sheet SOP_01
TEST_29: R29.1 ; off-sheet TEST_29
TEST_30: R30.1 ; off-sheet TEST_30
NetC28_2: C28.2 R50.1 R51.2 U3.5(NR/FB)
NetC33_1: C33.1 J6.6 J6.7 J6.8 J6.9 J6.10 J6.11 R52.1
NetD2_2: D2.2(A) L5.2
NetD3_2: D3.2(A) R49.2
NetD4_1: D4.1(K) R54.1
NetD5_1: D5.1(K) R58.1
NetD6_1: D6.1(K) R57.1
NetD7_1: D7.1(K) R55.1
NetJ6_1: J6.1 L5.1
NetJ6_5: J6.5 L6.2
NetP1_1: P1.1 R29.2
NetP1_2: P1.2 R30.2
NetP1_4: P1.4 R34.2
NetP1_5: P1.5 R36.2
NetP1_7: P1.7 R40.2
NetP1_8: P1.8 R43.2
NetP1_9: P1.9 R45.2
NetP1_10: P1.10 R46.2
NetP2_2: P2.2 R31.1
NetP2_3: P2.3 R32.1
NetP2_5: P2.5 R37.1
NetP2_6: P2.6 R39.1
NetP2_7: P2.7 R41.1
NetP2_10: P2.10 R47.1
NetP3_3: P3.3 R33.2
NetP3_4: P3.4 R35.2
NetP3_5: P3.5 R38.2
NetP3_7: P3.7 R42.2
NetP3_8: P3.8 R44.2
NetQ1_1: Q1.1(G) R56.2
NetQ1_3: Q1.3(D) R54.2
NetQ2_1: Q2.1(G) R59.2
NetQ2_3: Q2.3(D) R58.2
NetQ3_1: Q3.1(G) R60.2
NetQ3_3: Q3.3(D) R57.2
NetR53_1: R53.1 SW1.1 SW1.2
NetR61_2: R61.2 SW2.1
NetR62_2: R62.2 SW3.1

Not connected (* = marked no-connect by the designer): J6 2* 3* 4*; P1 3* 6*; P2 4* 8* 9*; P3 2* 6* 9* 10*; P4 3* 4* 5* 6* 7* 8* 9* 10*

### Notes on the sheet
- LAUNCHPAD  INTERFACE
- GND
- IRQ
- CS
- RESET
- MOSI
- MISO
- GPIO
- POWER MANAGEMENT
- MICRO USB
- Auto Select 5V
- From USB or LP
- FACTORY RESET
- LEDs
- PUSH BUTTONS

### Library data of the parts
C28 = GRM1555C1H150JA01D: CAP, CERM, 15 pF, 50 V, +/- 5%, C0G/NP0, 0402; Manufacturer: MuRata; Polarized: N; CompType: Capacitor; Value: 15pF; U/M: EA; Cap_F: 0.000000000015; Tolerance_%: 5; Value1: Unknown; VDC_V: 50; Value2: 50V; TaMin_C: -55; TaMax_C: 125
C29 C32 = GRM21BR61A106KE19L: CAP, CERM, 10 µF, 10 V, +/- 10%, X5R, 0805; Manufacturer: MuRata; Polarized: N; CompType: Capacitor; Value: 10uF; U/M: EA; Cap_F: 0.00001; Tolerance_%: 10; ESR_ohm: 0.002; Value1: 0.002 ohm; Value2: 10V; TaMin_C: -55; TaMax_C: 85; Cap_Case: 0805
C30 C31 = GRM31CR60J107ME39L: CAP, CERM, 100 µF, 6.3 V, +/- 20%, X5R, 1206; Manufacturer: MuRata; Polarized: N; CompType: Capacitor; Value: 100uF; U/M: EA; Cap_F: 0.0001; Tolerance_%: 20; ESR_ohm: 0.003; Value1: 0.003 ohm; VDC_V: 6.3; Value2: 6.3V; TaMin_C: -55; TaMax_C: 85
C33 = GRM188R61H102KA01D: CAP, CERM, 1000 pF, 50 V, +/- 10%, X5R, 0603; Manufacturer: MuRata; Polarized: N; CompType: Capacitor; Value: 1000pF; U/M: EA; Cap_F: 0.000000001; Tolerance_%: 10; Value1: Unknown; VDC_V: 50; Value2: 50V; TaMin_C: -55; TaMax_C: 85
D1 D2 = MBR130T1G: Diode, Schottky, 30 V, 1 A, SOD-123; Manufacturer: ON Semiconductor; U/M: EA; Vf_V: 0.47; Value: 30V; Value1: 1A; Value2: 0.47V; Io_A: 1; Vr_V: 30; TJmax_C: 125; RJC_CperW: 108
D3 = SML-311UTT86: LED, Red, SMD; Manufacturer: Rohm; Type: AlInGaP; Vf_V: 1.8; Value2: 1.8V; Io_A: 0.002; Value1: W; U/M: EA
D4 = 150060RS75000: LED, Red, SMD; Manufacturer: Wurth Elektronik; Type: AlInGaP; Vf_V: 2; Value2: 2V; Io_A: 0.03; Vr_V: 5; Tjmax_C: 85; Power_TotalModule: 0.072; Value1: 0.072W; Angle: 140; U/M: EA
D5 = 150060GS75000: LED, Green, SMD; Manufacturer: Wurth Elektronik; Type: InGaN; Vf_V: 3.2; Value2: 3.2V; Io_A: 0.02; Tjmax_C: 85; Value1: W; Angle: 140; U/M: EA
D6 = 150060YS75000: LED, Yellow, SMD; Manufacturer: Wurth Elektronik eiSos; Type: AlInGaP; Vf_V: 2; Value2: 2V; Io_A: 0.02; Value1: W; U/M: EA
D7 = CD0603-B00340: Diode, Schottky, 45 V, 0.03 A, 0603 Diode; Manufacturer: Bourns; U/M: EA; Vf_V: 0.37; Value: 45V; Value1: 0.03A; Value2: 0.37V; Io_A: 0.03; Vr_V: 45; TJmax_C: 125
J6 = 105017-0001: Connector, Receptacle, Micro-USB Type B, R/A, Bottom Mount SMT; Manufacturer: Molex; SymbolCreator: a0412235; U/M: EA
J7 = TSW-103-07-G-S: Header, 100mil, 3x1, Gold, TH; Manufacturer: Samtec; SymbolCreator: a0799628; U/M: EA
J8 = HMTSW-102-07-G-S-240: Header, 100mil, 2x1, Gold, TH; Manufacturer: Samtec; SymbolCreator: a0412235; U/M: EA
L5 L6 = MMZ2012R300A: Ferrite Bead, 30 ohm @ 100 MHz, 1.5 A, 0805; Manufacturer: TDK; Imax_A: 1.5; DCR_ohm: 0.05; Value1: 0.05 ohm; Value2: 1.5A; ZTyp@100MHz_Ohm: 30
P1-P4 = SSW-110-23-F-S: Connector, Receptacle, 100mil, 10x1, Gold plated, TH; Manufacturer: Samtec; SymbolCreator: a0411947; U/M: EA
Q1-Q3 = BSS138: MOSFET, N-CH, 50 V, 0.22 A, SOT-23; Manufacturer: Fairchild Semiconductor; Alternate Manufacturer: None; U/M: EA; ChType: N; Value: 50V; VdsMax_V: 50; Value1: 6 ohm; Rdson45_ohm: 6; Value2: 1.7 nC; QgTyp_nC: 1.7; Vgs_V: 20; IdsMax_A: 0.22
R28 = CRCW0603100KFKEA: RES, 100 k, 1%, 0.1 W, 0603; Manufacturer: Vishay-Dale; CompType: Resistor; Value: 100k; Res_ohm: 100000; Tolerance_%: 1; Power_W: 0.1; Value2: 0.1W; VDC_V: 75; TempCo: 100 ppm/C; EIA_Code: E96; U/M: EA
R29-R37 R39-R41 R43 R45-R47 = ERJ-2GE0R00X: as R1 on sheet 1.Engine
R38 R44 = CRCW04021K00JNED: as R18 on sheet 1.Engine
R42 = ERJ-2GE0R00X: RES, 0, 5%, 0.063 W, 0402; Manufacturer: Panasonic; CompType: Resistor; Value_Code: 0000; Tolerance_%: 5; Power_W: 0.063; Value2: 0.063W; VDC_V: 50; TempCo: 600 ppm/C; EIA_Code: E24; U/M: EA
R48 = CRM0805-FX-R100ELF: RES, 0.1, 1%, 0.25 W, 0805; Manufacturer: Bourns; CompType: Resistor; Value: 0.1; Value_Code: R100; Tolerance_%: 1; Power_W: 0.25; Value2: 0.25W; VDC_V: 0; TempCo: 150 ppm/C; EIA_Code: E96; U/M: EA
R49 R54 R57 = CRCW0603270RJNEA: RES, 270, 5%, 0.1 W, 0603; Manufacturer: Vishay-Dale; CompType: Resistor; Value: 270; Value_Code: 270R; Tolerance_%: 5; Power_W: 0.1; Value2: 0.1W; VDC_V: 75; TempCo: 200 ppm/C; EIA_Code: E24; U/M: EA
R50 = CRCW040251K0JNED: RES, 51 k, 5%, 0.063 W, 0402; Manufacturer: Vishay-Dale; CompType: Resistor; Value: 51k; Res_ohm: 51000; Value_Code: 51k0; Tolerance_%: 5; Power_W: 0.063; Value2: 0.063W; VDC_V: 50; TempCo: 200 ppm/C; EIA_Code: E24; U/M: EA
R51 = CRCW040230K1FKED: RES, 30.1 k, 1%, 0.063 W, 0402; Manufacturer: Vishay-Dale; CompType: Resistor; Value: 30.1k; Res_ohm: 30100; Value_Code: 30k1; Tolerance_%: 1; Power_W: 0.063; Value2: 0.063W; VDC_V: 50; TempCo: 100 ppm/C; EIA_Code: E96; U/M: EA
R52 = CRCW0402100KJNED: as R7 on sheet 1.Engine
R53 R61 R62 = ERJ-2RKF1000X: RES, 100, 1%, 0.1 W, 0402; Manufacturer: Panasonic; CompType: Resistor; Value: 100; Value_Code: 100R; Tolerance_%: 1; Power_W: 0.1; Value2: 0.1W; VDC_V: 50; TempCo: 100 ppm/C; EIA_Code: E96; U/M: EA
R55 = ERJ-3GEY0R00V: RES, 0, 5%, 0.1 W, 0603; Manufacturer: Panasonic; CompType: Resistor; Value: 0; Value_Code: 0000; Tolerance_%: 5; Power_W: 0.1; Value2: 0.1W; VDC_V: 50; TempCo: 600 ppm/C; EIA_Code: E24; U/M: EA
R56 R59 R60 = CRCW040210K0JNED: as R3 on sheet 1.Engine
R58 = CRCW0603220RJNEA: RES, 220, 5%, 0.1 W, 0603; Manufacturer: Vishay-Dale; CompType: Resistor; Value: 220; Value_Code: 220R; Tolerance_%: 5; Power_W: 0.1; Value2: 0.1W; VDC_V: 75; TempCo: 200 ppm/C; EIA_Code: E24; U/M: EA; AEC Category: Q200
SW1 = EVQ-PSD02K: Switch, Tactile, SPST-NO, SMT; Manufacturer: Panasonic; SymbolCreator: a0799628; VDC_V: 12; SwitchFunction: Off-Mom; PositionCount: 1; CurrentRating_mA: 50
SW2 SW3 = MJTP1117: Switch, SPST-NO, Off-Mom, 1 Pos, 0.05A, 12VDC, TH; Manufacturer: APEM; SymbolCreator: a0799628; VDC_V: 12; PositionCount: 1; CurrentRating_mA: 50
TP5 = TP_H0.45P0.75: as TP1 on sheet 1.Engine
U3 = TPS79601DCQR: Ultralow-Noise, High PSRR, Fast, RF, 1A, Low-Dropout Linear Regulator, DCQ0006A; Manufacturer: Texas Instruments; SymbolCreator: Altium; CompType: IC; U/M: EA

## Sheet EVM_Hardware.SchDoc: EVM_Hardware
size 431 x 279 mm; Date: Not shown in title block; ApprovedBy: Not shown in title block; CheckedBy: Not shown in title block; Author: Not shown in title block; CompanyName: Not shown in title block; Engineer: Not shown in title block; Organization: Not shown in title block; Address1: Not shown in title block; Address2: Not shown in title block; Address3: Not shown in title block; Address4: Not shown in title block; DocumentNumber: 4; Revision: Use project parameter SCH_Rev; SheetNumber: 4; SheetTotal: 4; PageSetup: Record=PageOptions¦CenterHorizontal=True¦CenterVertical=True¦PrintScale=1.00¦XCorrection=1.00¦YCorrection=1.00¦PrintKind=0¦BorderSize=5000000¦LeftOffset=0¦BottomOffset=0¦Orientation=2¦PaperLength=1000¦PaperWidth=1000¦Scale=100¦PaperSource=15¦PrintQuality=600¦MediaType=1¦DitherType=10¦PaperKind=Letter¦PrintScaleMode=1
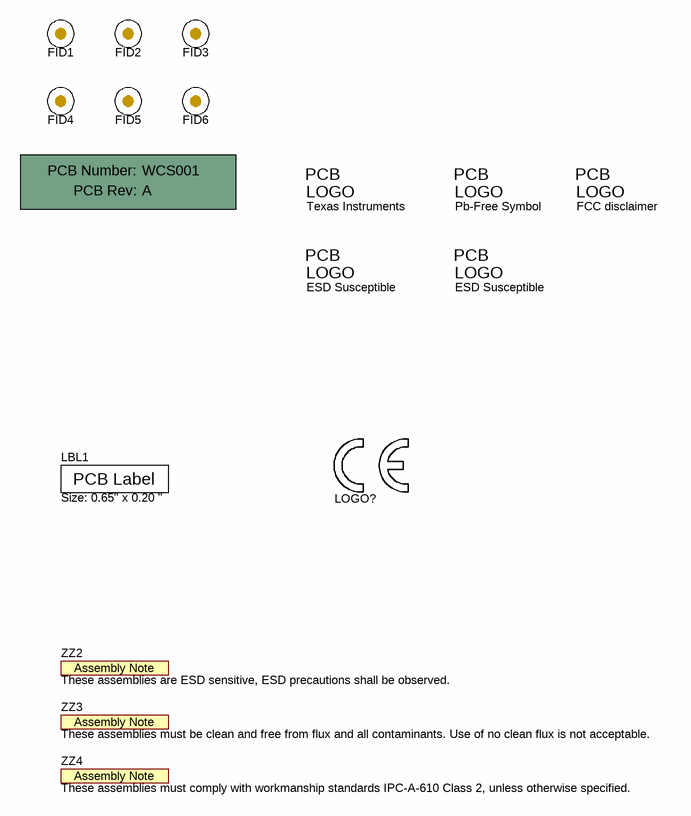
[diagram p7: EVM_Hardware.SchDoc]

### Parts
!PCB1  Printed Circuit Board  (value not drawn)  (mechanical)
FID1  Fiducial  [Fiducial10-20]  (value not drawn)
FID2  Fiducial  [Fiducial10-20]  (value not drawn)
FID3  Fiducial  [Fiducial10-20]  (value not drawn)
FID4  Fiducial  [Fiducial10-20]  (value not drawn)
FID5  Fiducial  [Fiducial10-20]  (value not drawn)
FID6  Fiducial  [Fiducial10-20]  (value not drawn)
LBL1  Size: 0.65" x 0.20 "  [Label_650x200]
Logo1  Texas Instruments  [TI_Stacked_Overlay_Small]  (no BOM)
Logo2  Pb-Free Symbol  [Pb-Free_Overlay_Small]  (no BOM)
Logo3  FCC disclaimer  [FCC_disclaimer]  (no BOM)
Logo4  ESD Susceptible  [ESD_Overlay_Small]  (no BOM)
Logo5  ESD Susceptible  [ESD_Overlay_Small]  (no BOM)
LOGO?  CE Mark  [CE_Mark_5mm]  (value not drawn)  (no BOM)
ZZ2  These assemblies are ESD sensitive, ESD precautions shall be observed.  [AssemblyNote]  (no BOM)
ZZ3  These assemblies must be clean and free from flux and all contaminants. Use of no clean flux is not acceptable.  [AssemblyNote]  (no BOM)
ZZ4  These assemblies must comply with workmanship standards IPC-A-610 Class 2, unless otherwise specified.  [AssemblyNote]  (no BOM)

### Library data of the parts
!PCB1 = PCB: Manufacturer: Any; PartNumber: WCS001; SymbolCreator: a0412235
FID1-FID6 = Fiducial: Fiducial mark.  There is nothing to buy or mount.; SymbolCreator: codlsc
LBL1 = THT-14-423-10: Thermal Transfer Printable Labels, 0.650" W x 0.200" H - 10,000 per roll; Manufacturer: Brady; SymbolCreator: a0412235; CompType: Label
Logo1 = TI_Logo: Texas Instrument Corporate Signature; SymbolCreator: codlsc
Logo2 = Pb-Free: SymbolCreator: a0412235
Logo3 = FCC_disclaimer: SymbolCreator: codlsc
Logo4 Logo5 = ESD_Susceptible: ESD Susceptible Symbol; SymbolCreator: a0412235
LOGO? = CE Mark: SymbolCreator: a0412235
ZZ2-ZZ4 = AssemblyNote: SymbolCreator: codlsc

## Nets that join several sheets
GND: 1.Engine (51 pins), 2.HOST INTERFACE (19 pins)
VBAT_CC: 1.Engine (12 pins), 2.HOST INTERFACE (C30.1 C31.1 J8.2 R48.2)
VCC_BRD: 1.Engine (5 pins), 2.HOST INTERFACE (9 pins)
VCC_LDO_3V3: 1.Engine (R6.2), 2.HOST INTERFACE (5 pins)
VCC_MCU_5V: 1.Engine (R13.1), 2.HOST INTERFACE (D1.2 P4.1)
CC_IRQ: 1.Engine (R16.1 U2.15), 2.HOST INTERFACE (R31.2)
CC_nHIB: 1.Engine (U2.2), 2.HOST INTERFACE (R28.1 R38.1 R59.1 SW2.2)
CC_nRESET: 1.Engine (C27.1 R26.2 U2.32), 2.HOST INTERFACE (D7.2 R60.1 SW3.2)
CC_NWP_UART_TX: 1.Engine (U2.62), 2.HOST INTERFACE (R40.1)
CC_SPI_CLK: 1.Engine (U2.5), 2.HOST INTERFACE (R42.1)
CC_SPI_CS: 1.Engine (U2.8), 2.HOST INTERFACE (R32.2)
CC_SPI_DIN: 1.Engine (U2.6), 2.HOST INTERFACE (R39.2)
CC_SPI_DOUT: 1.Engine (R15.1 U2.7), 2.HOST INTERFACE (R41.2)
CC_UART1_CTS: 1.Engine (U2.61), 2.HOST INTERFACE (R34.1)
CC_UART1_RTS: 1.Engine (R11.1 U2.50), 2.HOST INTERFACE (R36.1)
CC_UART1_RX: 1.Engine (R9.2 U2.57), 2.HOST INTERFACE (R35.1)
CC_UART1_TX: 1.Engine (R8.2 U2.55), 2.HOST INTERFACE (R33.1)
CC_WL_UART_TX: 1.Engine (U2.60), 2.HOST INTERFACE (R43.1)
CC_WLRS232_RX: 1.Engine (U2.59), 2.HOST INTERFACE (R46.1)
CC_WLRS232_TX: 1.Engine (U2.58), 2.HOST INTERFACE (R45.1)
MCU_RESET_IN: 1.Engine (R12.2), 2.HOST INTERFACE (R37.2 R47.2 R55.2)
SOP_01: 1.Engine (J4.3 R21.2 R24.1 U2.34), 2.HOST INTERFACE (R44.1 R56.1 SW1.3 SW1.4)
TEST_29: 1.Engine (U2.29), 2.HOST INTERFACE (R29.1)
TEST_30: 1.Engine (U2.30), 2.HOST INTERFACE (R30.1)

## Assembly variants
001: not fitted C23 FID1 FID2 FID3 FID4 FID5 FID6 J3 J4 J5 R1 R6 R9 R11 R14 R15 R18 R19 R20 R29 R30 R37 R45 R46 R47 R48 Y2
